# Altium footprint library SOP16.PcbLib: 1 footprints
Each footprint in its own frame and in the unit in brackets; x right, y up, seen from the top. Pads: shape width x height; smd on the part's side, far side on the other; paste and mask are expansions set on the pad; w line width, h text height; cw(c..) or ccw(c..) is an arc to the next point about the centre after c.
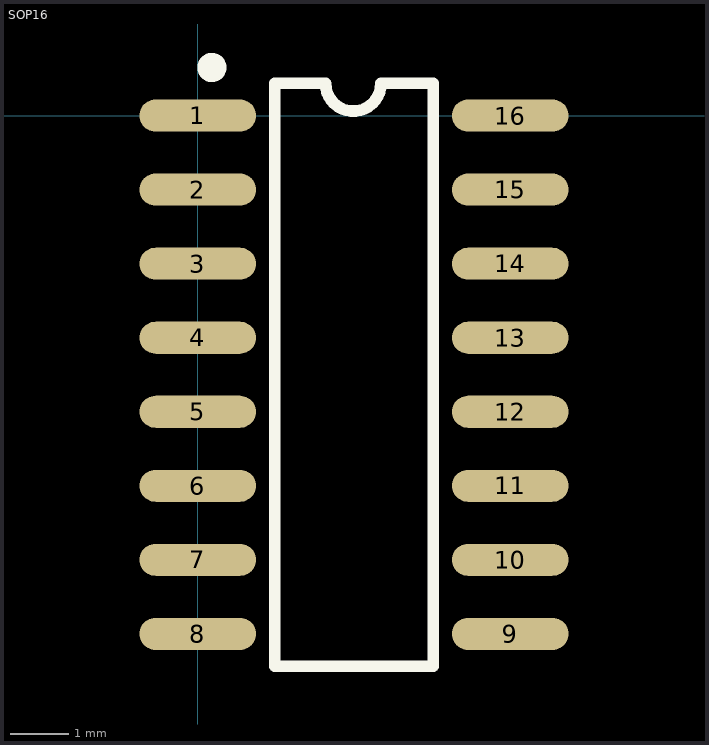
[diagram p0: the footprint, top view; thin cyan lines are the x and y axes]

## SOP16 [mm]
pads (16):
  oval 2x0.55 smd: 1(0,0) 2(0,-1.27) 3(0,-2.54) 4(0,-3.81) 5(0,-5.08) 6(0,-6.35) 7(0,-7.62) 8(0,-8.89) 9(5.359,-8.89) 10(5.359,-7.62) 11(5.359,-6.35) 12(5.359,-5.08) 13(5.359,-3.81) 14(5.359,-2.54) 15(5.359,-1.27) 16(5.359,0)
Top Overlay:
  circle w0.25: c0.242,0.825 r0.125
  lines w0.2: 2.184,0.555 1.321,0.555 1.321,-9.445 4.039,-9.445 4.039,0.555 3.142,0.555 ; 2.192,0.552 ccw(c2.667,0.551) 3.142,0.552
3D body "SO-16.STEP": height 1.45, standoff 0, extent -0.254,-9.436 5.651,0.546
